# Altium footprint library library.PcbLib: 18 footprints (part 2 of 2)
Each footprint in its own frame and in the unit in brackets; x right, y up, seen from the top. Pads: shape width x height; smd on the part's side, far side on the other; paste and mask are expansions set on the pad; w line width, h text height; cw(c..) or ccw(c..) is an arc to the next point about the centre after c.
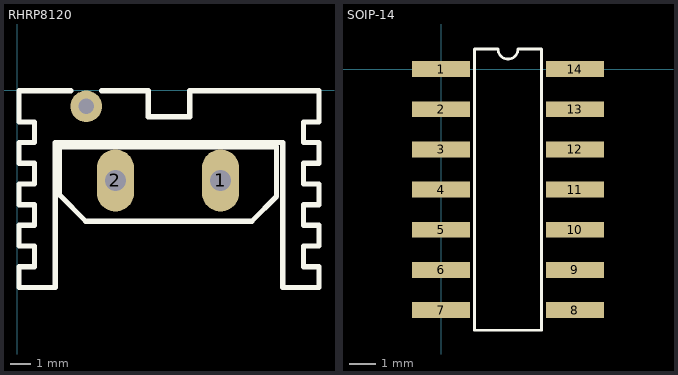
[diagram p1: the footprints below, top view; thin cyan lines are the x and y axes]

## RHRP8120 [mm]
pads (3):
  oval 1.8x3 hole 1: 1(9.819,-4.366) 2(4.739,-4.366)
  round 1.524 hole 0.762: ""(3.328,-0.784)
Top Overlay:
  lines w0.254: 2.578,-0.034 0.078,-0.034 0.078,-1.534 0.828,-1.534 0.828,-2.534 0.078,-2.534 0.078,-3.534 0.828,-3.534 0.828,-4.534 0.078,-4.534 0.078,-5.534 0.828,-5.534 0.828,-6.534 0.078,-6.534 0.078,-7.534 0.828,-7.534 0.828,-8.534 0.078,-8.534 0.078,-9.534 1.828,-9.534 1.828,-2.534 12.828,-2.534 12.828,-9.534 14.578,-9.534 14.578,-8.534 13.828,-8.534 13.828,-7.534 14.578,-7.534 14.578,-6.534 13.828,-6.534 13.828,-5.534 14.578,-5.534 14.578,-4.534 13.828,-4.534 13.828,-3.534 14.578,-3.534 14.578,-2.534 13.828,-2.534 13.828,-1.534 14.578,-1.534 14.578,-0.034 10.578,-0.034 8.328,-0.034 8.328,-1.284 6.328,-1.284 6.328,-0.034 4.078,-0.034 ; 2.003,-2.734 2.028,-2.759 2.028,-5.059 3.303,-6.334 11.328,-6.334 12.528,-5.134 12.528,-2.734 2.003,-2.734

## SOIP-14 [mm]
pads (14):
  rect 2.2x0.6 smd: 1(0,0) 2(0,-1.524) 3(0,-3.048) 4(0,-4.572) 5(0,-6.096) 6(0,-7.62) 7(0,-9.144) 8(5.08,-9.144) 9(5.08,-7.62) 10(5.08,-6.096) 11(5.08,-4.572) 12(5.08,-3.048) 13(5.08,-1.524) 14(5.08,0)
Top Overlay:
  lines w0.1: 1.27,-9.906 1.27,0.762 1.835,0.762 2.159,0.762 ccw(c2.54,0.762) 2.921,0.762 3.245,0.762 3.81,0.762 3.81,-9.906 3.245,-9.906 1.835,-9.906 1.27,-9.906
